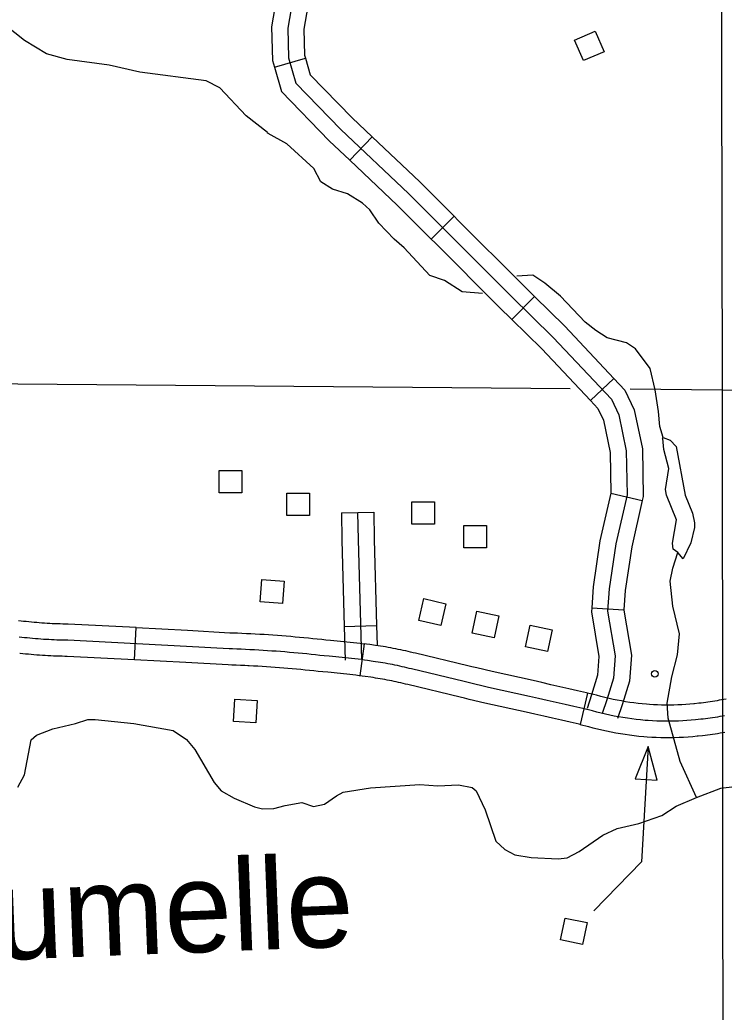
# Model space of a CAD drawing. Extents: x -19 to 366, y -4 to 359.
# Drawn here: x 135.775 to 136.395, y 193.481 to 194.354 of the extents above; entities that cross this region are included whole.
import ezdxf

# ---------------------------------------------------------------- set-up
doc = ezdxf.new("R2010")
doc.units = 0
for name, color, linetype in [('Level 31', 7, 'Continuous'), ('Level 32', 7, 'Continuous'), ('Level 35', 7, 'Continuous'), ('Level 5', 7, 'Continuous'), ('Level 56', 7, 'Continuous'), ('Level 60', 7, 'Continuous')]:
    doc.layers.add(name, color=color, linetype=linetype)

msp = doc.modelspace()

# ---------------------------------------------------------------- linework, layer by layer
at = {"layer": 'Level 31'}
for p, q in [((135.87596, 193.79108), (135.87742, 193.81945)), ((136.07805, 193.80523), (136.07422, 193.77708)), ((136.27465, 193.76171), (136.26802, 193.73409))]:
    msp.add_line(p, q, dxfattribs=at)
for points in [[(135.77854, 193.82495), (135.77632, 193.82521), (135.77405, 193.8255)], [(135.87742, 193.81945), (135.81781, 193.82252), (135.81521, 193.82255), (135.8129, 193.8226), (135.81061, 193.82265), (135.80831, 193.82272), (135.80604, 193.82281), (135.80374, 193.82291), (135.80143, 193.82302), (135.79915, 193.82315), (135.79688, 193.82329), (135.79459, 193.82345), (135.7923, 193.82362), (135.79002, 193.8238), (135.78773, 193.824), (135.78543, 193.82422), (135.78314, 193.82444), (135.78086, 193.82469), (135.77859, 193.82494), (135.77852, 193.82495)], [(135.87742, 193.81945), (135.92262, 193.81712), (135.95985, 193.81497), (135.96276, 193.81487), (135.96664, 193.81472), (135.97057, 193.81456), (135.97447, 193.81438), (135.97726, 193.81425)], [(136.07562, 193.79123), (136.07267, 193.79161), (136.06987, 193.79196), (136.06706, 193.7923), (136.06426, 193.79262), (136.06146, 193.79292), (136.05863, 193.79322), (136.05583, 193.7935), (136.053, 193.79376), (136.0502, 193.79401), (136.04737, 193.79424), (136.04296, 193.79458), (136.03913, 193.79502), (136.0353, 193.79544), (136.03146, 193.79584), (136.02763, 193.79624), (136.02378, 193.79661), (136.01996, 193.79698), (136.01611, 193.79732), (136.01226, 193.79766), (136.00842, 193.79798), (136.00457, 193.79828), (136.00075, 193.79857), (135.99688, 193.79885), (135.99304, 193.79911), (135.98919, 193.79935), (135.98535, 193.79959), (135.98151, 193.7998), (135.97764, 193.80001), (135.9738, 193.8002), (135.96995, 193.80037), (135.96609, 193.80053), (135.96225, 193.80067), (135.95919, 193.80078), (135.92185, 193.80293), (135.81736, 193.80832), (135.81499, 193.80835), (135.81259, 193.8084), (135.81022, 193.80846), (135.80783, 193.80853), (135.80546, 193.80862), (135.80309, 193.80872), (135.80069, 193.80884), (135.79832, 193.80897), (135.79595, 193.80912), (135.79357, 193.80928), (135.7912, 193.80946), (135.78882, 193.80965), (135.78645, 193.80986), (135.78408, 193.81008), (135.7817, 193.81031), (135.77932, 193.81056), (135.77697, 193.81083), (135.77459, 193.81111)], [(135.97726, 193.81425), (135.97836, 193.81419), (135.98228, 193.81399), (135.98617, 193.81377), (135.99008, 193.81353), (135.99397, 193.81328), (135.99787, 193.81302), (136.0018, 193.81274), (136.00567, 193.81244), (136.00956, 193.81214), (136.01346, 193.81181), (136.01736, 193.81147), (136.02127, 193.81112), (136.02514, 193.81075), (136.02905, 193.81037), (136.03292, 193.80997), (136.03682, 193.80956), (136.04071, 193.80913), (136.0443, 193.80872), (136.0485, 193.8084), (136.05141, 193.80816), (136.05428, 193.80791), (136.05719, 193.80764), (136.06007, 193.80735), (136.06296, 193.80705), (136.06584, 193.80673), (136.06872, 193.8064), (136.0716, 193.80606), (136.07447, 193.8057), (136.07749, 193.80531), (136.07805, 193.80523)], [(136.17717, 193.78392), (136.17284, 193.78496), (136.16925, 193.78582), (136.12321, 193.79685), (136.12114, 193.79737), (136.11893, 193.7979), (136.11675, 193.79841), (136.11458, 193.79891), (136.11239, 193.7994), (136.11019, 193.79987), (136.10799, 193.80032), (136.10581, 193.80077), (136.10359, 193.8012), (136.10138, 193.80161), (136.09917, 193.80201), (136.09697, 193.8024), (136.09475, 193.80277), (136.09252, 193.80313), (136.09032, 193.80348), (136.0881, 193.80381), (136.0831, 193.80453), (136.08023, 193.80493), (136.07805, 193.80523)], [(135.87596, 193.79108), (135.8169, 193.79412), (135.81477, 193.79415), (135.81229, 193.79419), (135.80984, 193.79426), (135.80735, 193.79433), (135.80487, 193.79443), (135.80243, 193.79453), (135.79995, 193.79465), (135.79749, 193.79479), (135.79502, 193.79494), (135.79256, 193.79511), (135.7901, 193.7953), (135.78763, 193.7955), (135.78517, 193.79571), (135.78272, 193.79594), (135.78025, 193.79618), (135.77778, 193.79644), (135.77535, 193.79672), (135.77521, 193.79673)], [(135.97585, 193.78587), (135.97312, 193.78601), (135.96934, 193.78618), (135.96553, 193.78634), (135.96174, 193.78648), (135.95853, 193.78659), (135.92107, 193.78875), (135.87596, 193.79108)], [(136.39501, 193.74182), (136.39294, 193.74145), (136.39085, 193.74108), (136.38877, 193.74073), (136.3867, 193.7404), (136.3846, 193.74008), (136.3825, 193.73977), (136.3804, 193.73948), (136.37833, 193.73921), (136.37623, 193.73895), (136.37412, 193.73871), (136.36959, 193.73821), (136.36581, 193.73785), (136.36203, 193.73755), (136.35827, 193.73731), (136.35449, 193.73713), (136.3507, 193.73701), (136.34692, 193.73695), (136.33924, 193.73701), (136.33557, 193.73712), (136.33177, 193.7373), (136.328, 193.73754), (136.32517, 193.73777), (136.32126, 193.73814), (136.31738, 193.73857), (136.31348, 193.73906), (136.30961, 193.73961), (136.30573, 193.74022), (136.30187, 193.74088), (136.29801, 193.7416), (136.29418, 193.74238), (136.29034, 193.74322), (136.28652, 193.74412), (136.28273, 193.74507), (136.27893, 193.74608), (136.27034, 193.74814), (136.26254, 193.74996), (136.25474, 193.75178), (136.24695, 193.75358), (136.23912, 193.75536), (136.23133, 193.75713), (136.2235, 193.7589), (136.18741, 193.76683), (136.16952, 193.77115), (136.16594, 193.77201), (136.11983, 193.78305), (136.11775, 193.78358), (136.11565, 193.78408), (136.11355, 193.78457), (136.11145, 193.78505), (136.10935, 193.78552), (136.10726, 193.78597), (136.10514, 193.78641), (136.10304, 193.78683), (136.10092, 193.78725), (136.0988, 193.78765), (136.09668, 193.78803), (136.09456, 193.7884), (136.09244, 193.78876), (136.0903, 193.7891), (136.08818, 193.78943), (136.08604, 193.78975), (136.08109, 193.79047), (136.07829, 193.79086), (136.07562, 193.79123)], [(136.07422, 193.77708), (136.07375, 193.77714), (136.07088, 193.77752), (136.06814, 193.77786), (136.06541, 193.77819), (136.06268, 193.7785), (136.05995, 193.7788), (136.05719, 193.77909), (136.05446, 193.77936), (136.05172, 193.77961), (136.04898, 193.77986), (136.04624, 193.78008), (136.04161, 193.78044), (136.03755, 193.7809), (136.03379, 193.78132), (136.02999, 193.78171), (136.02621, 193.7821), (136.02242, 193.78247), (136.01865, 193.78283), (136.01486, 193.78318), (136.01106, 193.7835), (136.00727, 193.78382), (136.00348, 193.78412), (135.9997, 193.7844), (135.9959, 193.78468), (135.9921, 193.78493), (135.98831, 193.78518), (135.98452, 193.78541), (135.98073, 193.78562), (135.97691, 193.78582), (135.97585, 193.78587)], [(136.27465, 193.76171), (136.27362, 193.76196), (136.26577, 193.7638), (136.25795, 193.76562), (136.25012, 193.76742), (136.24228, 193.76921), (136.23446, 193.77099), (136.22659, 193.77276), (136.1906, 193.78067), (136.17717, 193.78392)], [(136.1705, 193.7563), (136.16619, 193.75734), (136.16263, 193.7582), (136.11644, 193.76926), (136.11436, 193.76978), (136.11237, 193.77026), (136.11035, 193.77073), (136.10833, 193.7712), (136.10632, 193.77164), (136.10433, 193.77207), (136.10228, 193.77249), (136.10027, 193.7729), (136.09825, 193.7733), (136.09622, 193.77368), (136.09419, 193.77405), (136.09215, 193.7744), (136.09013, 193.77474), (136.08808, 193.77507), (136.08604, 193.77539), (136.08398, 193.7757), (136.07908, 193.77641), (136.07634, 193.77679), (136.07423, 193.77708)], [(136.26802, 193.73409), (136.26706, 193.73432), (136.25931, 193.73613), (136.25154, 193.73794), (136.24377, 193.73973), (136.23597, 193.74151), (136.22819, 193.74328), (136.22042, 193.74503), (136.18422, 193.75299), (136.1705, 193.7563)], [(136.36871, 193.75241), (136.36815, 193.75235), (136.36457, 193.752), (136.36101, 193.75172), (136.35748, 193.75149), (136.35393, 193.75132), (136.35037, 193.75121), (136.34686, 193.75115), (136.33952, 193.75121), (136.33612, 193.75132), (136.33256, 193.75149), (136.32902, 193.75171), (136.32642, 193.75192), (136.32271, 193.75227), (136.31905, 193.75268), (136.31537, 193.75314), (136.3117, 193.75366), (136.30802, 193.75424), (136.30438, 193.75486), (136.30073, 193.75555), (136.29711, 193.75628), (136.29348, 193.75708), (136.28987, 193.75792), (136.28627, 193.75882), (136.28241, 193.75985), (136.27465, 193.76171)], [(136.39637, 193.75655), (136.3944, 193.75616), (136.39242, 193.75579), (136.39046, 193.75543), (136.38845, 193.75508), (136.38647, 193.75475), (136.3845, 193.75443), (136.3825, 193.75413), (136.38051, 193.75384), (136.37851, 193.75356), (136.37652, 193.7533), (136.37453, 193.75305), (136.37254, 193.75282), (136.36871, 193.75241)], [(136.26802, 193.73409), (136.27545, 193.7323), (136.27918, 193.73132), (136.28317, 193.73031), (136.2872, 193.72937), (136.29124, 193.72848), (136.29529, 193.72766), (136.29936, 193.7269), (136.30343, 193.7262), (136.30752, 193.72556), (136.3116, 193.72498), (136.31571, 193.72447), (136.3198, 193.72401), (136.32393, 193.72362), (136.32697, 193.72337), (136.33099, 193.72312), (136.33501, 193.72293), (136.33896, 193.7228), (136.34698, 193.72274), (136.35104, 193.72281), (136.35506, 193.72293), (136.35907, 193.72313), (136.36305, 193.72338), (136.36705, 193.7237), (136.37104, 193.72408), (136.37178, 193.72416)], [(136.37178, 193.72416), (136.37571, 193.72459), (136.37792, 193.72485), (136.38013, 193.72512), (136.38229, 193.72541), (136.38449, 193.72571), (136.3867, 193.72603), (136.38889, 193.72636), (136.39107, 193.72671), (136.39324, 193.72708), (136.39543, 193.72746)]]:
    msp.add_lwpolyline(points, dxfattribs=at)
at = {"layer": 'Level 32'}
for p, q in [((135.9991, 194.31276), (136.02636, 194.32077)), ((136.06549, 194.23081), (136.08501, 194.25145)), ((136.13703, 194.16153), (136.15712, 194.18161)), ((136.2079, 194.0908), (136.22782, 194.11106)), ((136.27703, 194.01936), (136.29773, 194.0388)), ((136.29502, 193.93766), (136.32273, 193.93137)), ((136.05808, 193.92057), (136.08648, 193.92109)), ((136.27821, 193.837), (136.30655, 193.83511)), ((136.06061, 193.82047), (136.08901, 193.82125))]:
    msp.add_line(p, q, dxfattribs=at)
for points in [[(136.05558, 194.45945), (136.04231, 194.45164), (136.03575, 194.44114), (136.02525, 194.41619), (136.01673, 194.38141), (136.01082, 194.34728), (136.01148, 194.32102), (136.01804, 194.29871), (136.0574, 194.25801), (136.11709, 194.20156), (136.15055, 194.16809), (136.20697, 194.11164), (136.24436, 194.07489), (136.29553, 194.02041), (136.30209, 194.00662), (136.30865, 193.97512), (136.3093, 193.93639), (136.29946, 193.89307), (136.29356, 193.85369), (136.29225, 193.834), (136.29881, 193.79462), (136.29749, 193.77493), (136.29159, 193.75589), (136.28756, 193.74387)], [(136.01118, 194.41845), (136.00281, 194.38431), (135.99659, 194.34832), (135.99733, 194.3188), (135.9991, 194.31276)], [(136.03878, 194.41169), (136.03064, 194.3785), (136.02506, 194.34623), (136.02563, 194.32324), (136.02636, 194.32077)], [(136.02636, 194.32077), (136.03068, 194.30607), (136.06739, 194.26811), (136.08501, 194.25145)], [(135.9991, 194.31276), (136.0054, 194.29134), (136.04741, 194.24791), (136.06549, 194.23081)], [(136.08501, 194.25145), (136.127, 194.21175), (136.15712, 194.18161)], [(136.06549, 194.23081), (136.10719, 194.19138), (136.13703, 194.16153)], [(136.15712, 194.18161), (136.1606, 194.17813), (136.21697, 194.12173), (136.22782, 194.11106)], [(136.13703, 194.16153), (136.1405, 194.15805), (136.19696, 194.10156), (136.2079, 194.0908)], [(136.22782, 194.11106), (136.25452, 194.08482), (136.29773, 194.0388)], [(136.2079, 194.0908), (136.2342, 194.06495), (136.27703, 194.01936)], [(136.29773, 194.0388), (136.3074, 194.02852), (136.31564, 194.01119), (136.32282, 193.9767), (136.32353, 193.93492), (136.32273, 193.93137)], [(136.27703, 194.01936), (136.28365, 194.0123), (136.28853, 194.00206), (136.29447, 193.97354), (136.29507, 193.93787), (136.29502, 193.93766)], [(136.29502, 193.93766), (136.28549, 193.8957), (136.27942, 193.85522), (136.27821, 193.837)], [(136.32273, 193.93137), (136.31343, 193.89044), (136.30769, 193.85216), (136.30655, 193.83511)], [(136.05808, 193.92057), (136.05852, 193.89629), (136.06061, 193.82047)], [(136.07228, 193.92083), (136.07272, 193.89661), (136.07562, 193.79123)], [(136.08648, 193.92109), (136.08692, 193.89694), (136.08901, 193.82125)], [(136.27821, 193.837), (136.27796, 193.8333), (136.28452, 193.79391), (136.28343, 193.77754), (136.27807, 193.76025), (136.27409, 193.74838)], [(136.30655, 193.83511), (136.30653, 193.83471), (136.31309, 193.79532), (136.31155, 193.77232), (136.30511, 193.75153), (136.30103, 193.73936)], [(136.06061, 193.82047), (136.06142, 193.79083)], [(136.08901, 193.82125), (136.08948, 193.80408)]]:
    msp.add_lwpolyline(points, dxfattribs=at)
at = {"layer": 'Level 35'}
for points in [[(135.99301, 194.25528), (135.97424, 194.26991), (135.95114, 194.29456), (135.93894, 194.3008), (135.88061, 194.30854), (135.85368, 194.31453), (135.81694, 194.3196), (135.79871, 194.3246), (135.77924, 194.33641), (135.76238, 194.34978), (135.73228, 194.36369), (135.70673, 194.3773), (135.67096, 194.39149), (135.655, 194.39653), (135.63493, 194.39922), (135.56577, 194.39956), (135.52266, 194.40149), (135.50642, 194.40121), (135.48902, 194.40243)], [(136.18207, 194.11365), (136.16428, 194.11493), (136.14873, 194.12513), (136.13579, 194.12943), (136.11312, 194.15382), (136.10447, 194.16132), (136.0909, 194.17549), (136.0831, 194.18709), (136.07658, 194.19319), (136.06343, 194.20121), (136.05023, 194.20541), (136.03995, 194.21195), (136.03371, 194.22375), (136.00994, 194.24521), (135.9935, 194.25437), (135.99282, 194.25506)], [(136.341, 193.98666), (136.33802, 193.99654), (136.33704, 194.00981), (136.33406, 194.02873), (136.32957, 194.04763), (136.3168, 194.06486), (136.30878, 194.07004), (136.29169, 194.07468), (136.28176, 194.08096), (136.27256, 194.0884), (136.25062, 194.11117), (136.23708, 194.12253), (136.22644, 194.12963), (136.21224, 194.12874)], [(136.34049, 193.98598), (136.341, 193.98666), (136.34711, 193.98438), (136.3526, 193.97874), (136.3605, 193.936), (136.36682, 193.92018), (136.36872, 193.91173), (136.36871, 193.90749), (136.3655, 193.89419), (136.35867, 193.88002), (136.35392, 193.88552)], [(136.35392, 193.88552), (136.34987, 193.88858), (136.34928, 193.8937), (136.35267, 193.9143), (136.34398, 193.93596), (136.34301, 193.94115), (136.346, 193.95951), (136.34175, 193.97611), (136.34082, 193.98602)], [(136.37054, 193.66988), (136.35601, 193.70151), (136.34552, 193.73966), (136.34453, 193.75292), (136.34866, 193.77614), (136.35361, 193.79558), (136.35555, 193.81383), (136.34946, 193.83839), (136.34718, 193.86036), (136.34963, 193.87179), (136.35392, 193.88552)], [(135.77337, 193.67907), (135.77922, 193.68979), (135.78511, 193.72063), (135.78995, 193.72489), (135.80421, 193.73044), (135.82415, 193.73496), (135.83505, 193.73856), (135.84147, 193.73867), (135.87554, 193.73507), (135.91004, 193.72883), (135.92189, 193.72106), (135.92922, 193.71208), (135.94598, 193.68315), (135.95215, 193.67566), (135.9636, 193.66941), (135.98149, 193.66174), (135.9887, 193.65997), (135.99852, 193.66013), (136.00868, 193.66296), (136.02337, 193.66549), (136.03363, 193.66187), (136.04305, 193.66393), (136.05387, 193.67132)], [(136.05387, 193.67132), (136.05949, 193.67445), (136.0836, 193.67828), (136.127, 193.6813)], [(136.127, 193.6813), (136.1429, 193.68005), (136.16101, 193.68112), (136.17315, 193.67867), (136.1766, 193.67569), (136.18445, 193.65913), (136.194, 193.63159), (136.20169, 193.62413), (136.21046, 193.61934), (136.22486, 193.61693), (136.24869, 193.61582), (136.25661, 193.61671), (136.26709, 193.62221), (136.288, 193.6366), (136.30074, 193.64251), (136.31956, 193.64701), (136.33983, 193.65418), (136.35254, 193.66237), (136.37054, 193.66988), (136.39194, 193.67822), (136.41833, 193.68132)]]:
    msp.add_lwpolyline(points, dxfattribs=at)
at = {"layer": 'Level 5'}
for points in [[(136.39078, 195.03126), (136.39285, 194.02886)], [(135.39143, 194.03734), (136.25929, 194.02999)], [(136.31216, 194.02954), (136.39285, 194.02886)], [(136.39285, 194.02886), (136.39393, 193.02618)], [(136.39285, 194.02886), (137.24371, 194.01994)]]:
    msp.add_lwpolyline(points, dxfattribs=at)
at = {"layer": 'Level 56'}
for points in [[(136.28131, 194.3445), (136.28908, 194.32638), (136.27091, 194.31859), (136.26314, 194.3367)], [(135.95063, 193.93799), (135.95063, 193.95771), (135.9704, 193.95771), (135.9704, 193.93799)], [(136.01007, 193.91805), (136.01007, 193.93777), (136.02985, 193.93777), (136.02985, 193.91805)], [(136.12006, 193.91048), (136.12006, 193.93019), (136.13983, 193.93019), (136.13983, 193.91048)], [(136.16578, 193.88955), (136.16578, 193.90926), (136.18556, 193.90926), (136.18556, 193.88955)], [(135.98812, 193.86183), (136.00778, 193.86039), (136.00633, 193.84067), (135.98667, 193.84211)], [(136.12617, 193.82574), (136.13061, 193.84495), (136.14987, 193.8405), (136.14544, 193.82129)], [(136.17304, 193.81456), (136.17714, 193.83384), (136.19648, 193.82973), (136.19238, 193.81045)], [(136.21995, 193.80241), (136.22405, 193.8217), (136.24339, 193.81759), (136.23929, 193.7983)], [(135.98396, 193.75524), (135.98287, 193.73556), (135.96313, 193.73665), (135.96422, 193.75633)], [(136.31649, 193.6863), (136.33577, 193.68517), (136.32783, 193.71466)], [(136.25077, 193.54447), (136.25479, 193.56377), (136.27414, 193.55974), (136.27012, 193.54044)]]:
    msp.add_lwpolyline(points, close=True, dxfattribs=at)
msp.add_lwpolyline([(136.32783, 193.71466), (136.32188, 193.61335), (136.28019, 193.57014)], dxfattribs=at)
msp.add_circle((136.33379, 193.77872), 0.00284, dxfattribs=at)
at = {"layer": 'Level 60'}
for points in [[(139.44064, 1.53154), (139.25106, 10.14733), (139.06082, 18.76327), (138.86992, 27.37935), (138.67836, 35.99557), (138.48613, 44.61194), (138.29325, 53.22845), (138.09971, 61.84511), (137.9055, 70.46191), (137.71065, 79.07885), (137.51513, 87.69595), (137.31896, 96.31318), (137.12214, 104.93057), (136.92466, 113.54809), (136.72653, 122.16577), (136.52775, 130.78359), (136.32832, 139.40156), (136.12824, 148.01968), (135.9275, 156.63794), (135.72612, 165.25636), (135.5241, 173.87492), (135.32143, 182.49362), (135.11811, 191.11248), (134.91415, 199.73149), (134.70954, 208.35064), (134.50429, 216.96995), (134.2984, 225.5894), (134.09187, 234.209), (133.8847, 242.82876), (133.6769, 251.44866), (133.46845, 260.06872), (133.25937, 268.68892), (133.04965, 277.30928), (132.8393, 285.92978), (132.62831, 294.55044), (132.41669, 303.17125), (132.20444, 311.79221), (131.99156, 320.41333), (131.77805, 329.0346), (131.56391, 337.65601), (131.34914, 346.27759)], [(0, 189.51617), (7.11214, 189.52059), (14.22427, 189.53386), (21.33637, 189.55597), (28.44845, 189.58693), (35.56048, 189.62672), (42.67245, 189.67537), (49.78436, 189.73285), (56.89619, 189.79918), (64.00793, 189.87436), (71.11958, 189.95838), (78.23111, 190.05124), (85.34253, 190.15294), (92.45381, 190.26349), (99.56495, 190.38288), (106.67593, 190.51112), (113.78675, 190.6482), (120.89739, 190.79412), (128.00785, 190.94888), (135.11811, 191.11248), (142.22816, 191.28493), (149.33799, 191.46621), (156.44759, 191.65634), (163.55694, 191.85531), (170.66605, 192.06312), (177.77489, 192.27977), (184.88345, 192.50526), (191.99173, 192.73959), (199.09971, 192.98276), (206.20739, 193.23477), (213.31474, 193.49561), (220.42177, 193.7653), (227.52845, 194.04382), (234.63479, 194.33118), (241.74076, 194.62738), (248.84635, 194.93241), (255.95157, 195.24628), (263.05638, 195.56898), (270.16079, 195.90052), (277.26478, 196.24089), (284.36834, 196.5901), (291.47147, 196.94814), (298.57414, 197.31501), (305.67635, 197.69072), (312.77809, 198.07525), (319.87934, 198.46862), (326.9801, 198.87082), (334.08035, 199.28185), (341.18009, 199.7017)]]:
    msp.add_spline(points, degree=3, dxfattribs=at)

# ---------------------------------------------------------------- texts
at = {"layer": 'Level 35'}
msp.add_text('Maumelle', height=0.08, rotation=2.24324, dxfattribs=at).set_placement((135.60656, 193.52088))

doc.saveas('drawing.dxf')
